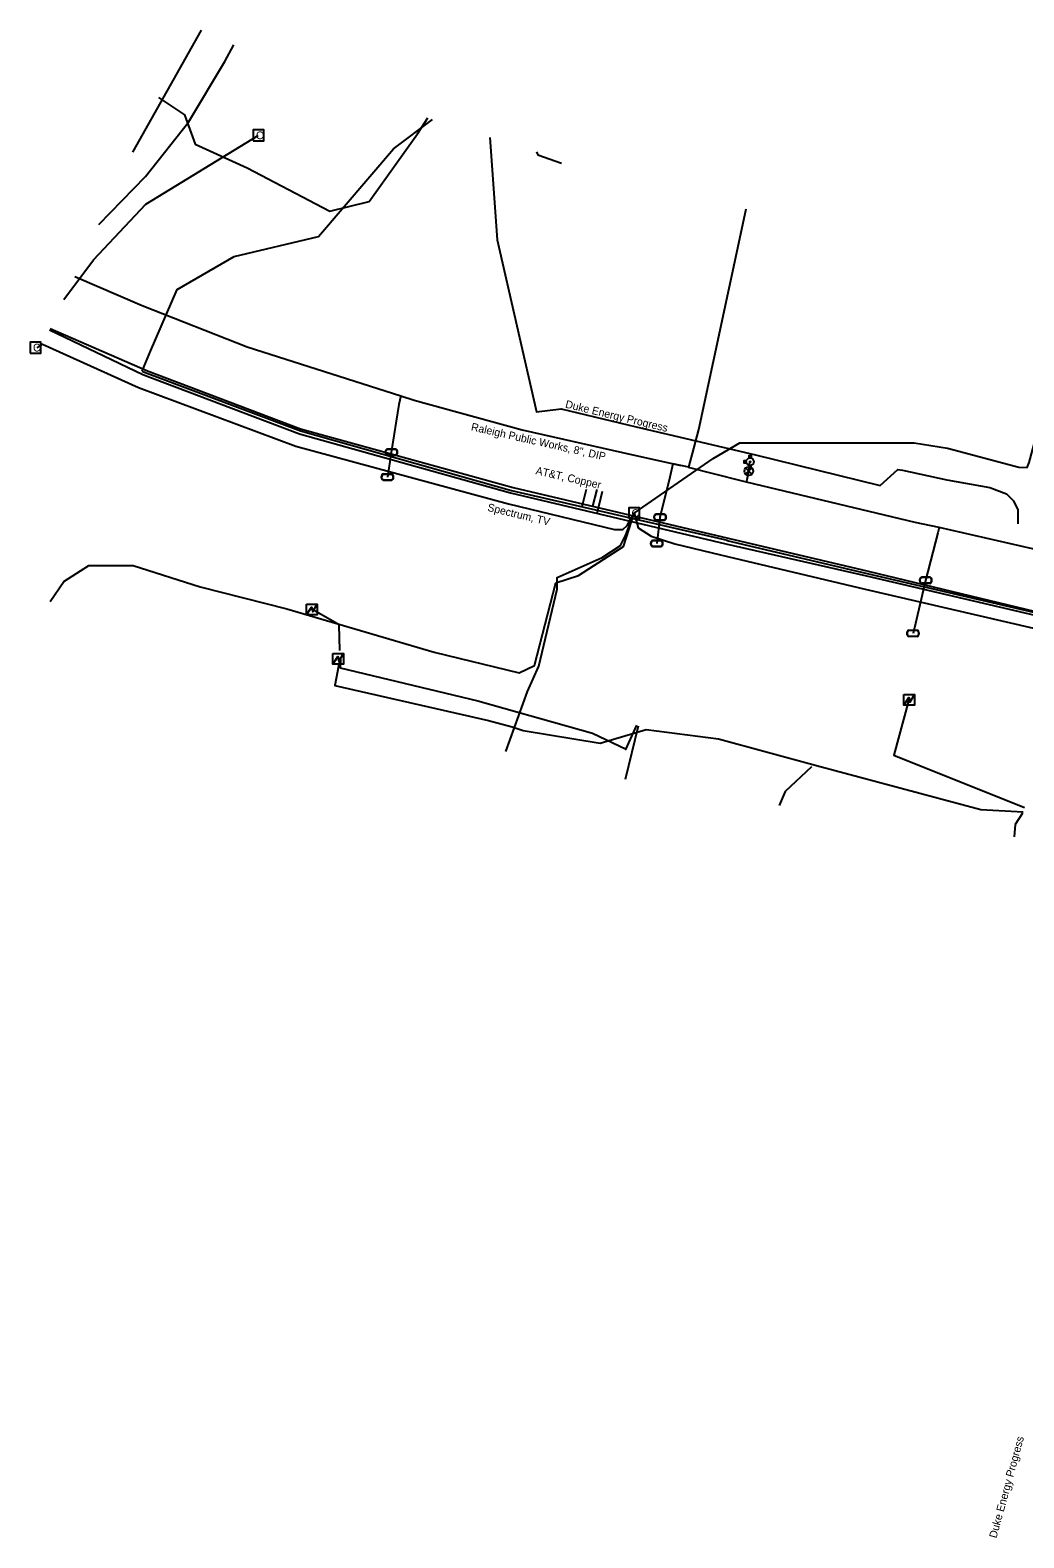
# Model space of a CAD drawing. Extents: x 2070721 to 2083039, y 729290 to 737883.
# Drawn here: x 2081558 to 2082068, y 735849 to 736623 of the extents above; entities that cross this region are included whole.
import ezdxf

# ---------------------------------------------------------------- set-up
doc = ezdxf.new("R2010")
doc.units = 0
for name, color, linetype in [('Cogo Default Point CELL', 7, 'Continuous'), ('COGO Default Point Elevation', 7, 'Continuous'), ('COGO Default Point Number', 7, 'Continuous'), ('Exist Utilities Gas UG Line SUE Cogo Point CELL', 7, 'Continuous'), ('Exist Utilities Gas Valve Cogo Elevation', 7, 'Continuous'), ('Exist Utilities Telephone Hand Hole Cogo Elevation', 7, 'Continuous'), ('Exist Utilities Telephone UG Cable SUE LOS C Cogo Number', 7, 'Continuous'), ('Exist Utilities Telephone UG FO Cogo Point CELL', 7, 'Continuous'), ('Exist Utilities TV Pedestal Cogo Elevation', 7, 'Continuous'), ('Exist Utilities TV UG Cable Cogo Point CELL', 7, 'Continuous'), ('Exist Utilities TV UG Cable SUE LOS C Cogo Comment', 7, 'Continuous'), ('Exist Utilities TV UG Cable SUE LOS C Cogo Elevation', 7, 'Continuous'), ('Exist Utilities Water Meter CELL', 7, 'Continuous'), ('Exist Utilities Water Meter Cogo Number', 7, 'Continuous')]:
    doc.layers.add(name, color=color, linetype=linetype)

msp = doc.modelspace()

# ---------------------------------------------------------------- linework, layer by layer
at = {"layer": 'Cogo Default Point CELL'}
for p, q in [((2081675.3, 736568.67), (2081675.3, 736568.67)), ((2081560.99, 736459.77), (2081560.99, 736459.77)), ((2081867.92, 736374.85), (2081867.92, 736374.85))]:
    msp.add_line(p, q, dxfattribs=at)
for points in [[(2081672.53, 736565.9), (2081678.07, 736565.9), (2081678.07, 736571.45), (2081672.53, 736571.45), (2081672.53, 736565.9)], [(2081558.22, 736456.99), (2081563.77, 736456.99), (2081563.77, 736462.55), (2081558.22, 736462.55), (2081558.22, 736456.99)], [(2081865.15, 736372.08), (2081870.7, 736372.08), (2081870.7, 736377.62), (2081865.15, 736377.62), (2081865.15, 736372.08)]]:
    msp.add_lwpolyline(points, dxfattribs=at)
at = {"layer": 'COGO Default Point Elevation'}
msp.add_lwpolyline([(2081928.26, 736398.02), (2081925.1, 736394.86), (2081926.68, 736396.44), (2081928.26, 736394.86), (2081925.1, 736398.02)], dxfattribs=at)
msp.add_circle((2081926.68, 736396.44), 2.23, dxfattribs=at)
at = {"layer": 'COGO Default Point Number'}
msp.add_line((2081927.4, 736401.2), (2081927.4, 736401.2), dxfattribs=at)
for points in [[(2081926.89, 736403.11), (2081926.89, 736404.4), (2081927.91, 736404.4), (2081927.91, 736403.09)], [(2081925.49, 736401.71), (2081924.2, 736401.71), (2081924.2, 736400.69), (2081925.49, 736400.69)], [(2081926.89, 736399.29), (2081926.89, 736398), (2081927.91, 736398), (2081927.91, 736399.31)]]:
    msp.add_lwpolyline(points, dxfattribs=at)
for radius in [1.98, 0.243]:
    msp.add_circle((2081927.4, 736401.2), radius, dxfattribs=at)
at = {"layer": 'Exist Utilities Gas Valve Cogo Elevation'}
for p, q in [((2081841.3, 736378.17), (2081843.56, 736387.2)), ((2081846.72, 736378.45), (2081848.94, 736386.91)), ((2081848.99, 736374.72), (2081851.73, 736386.2))]:
    msp.add_line(p, q, dxfattribs=at)
at = {"layer": 'Exist Utilities Telephone UG Cable SUE LOS C Cogo Number'}
for p, q in [((2081702.7, 736325.61), (2081702.7, 736325.61)), ((2081716.19, 736300.27), (2081716.19, 736300.27)), ((2082009, 736279.19), (2082009, 736279.19))]:
    msp.add_line(p, q, dxfattribs=at)
for points in [[(2081699.86, 736328.22), (2081705.41, 736328.22), (2081705.41, 736322.67), (2081699.86, 736322.67)], [(2081713.35, 736302.88), (2081718.9, 736302.88), (2081718.9, 736297.33), (2081713.35, 736297.33)], [(2082006.16, 736281.8), (2082011.71, 736281.8), (2082011.71, 736276.25), (2082006.16, 736276.25)]]:
    msp.add_lwpolyline(points, close=True, dxfattribs=at)
for points in [[(2081699.86, 736322.67), (2081702.5, 736326.61), (2081703.13, 736324.4), (2081705.41, 736328.22)], [(2081699.93, 736322.67), (2081702.5, 736326.4), (2081703.09, 736324.22), (2081705.41, 736328.07)], [(2081713.35, 736297.33), (2081715.99, 736301.27), (2081716.62, 736299.06), (2081718.9, 736302.88)], [(2081713.42, 736297.33), (2081715.99, 736301.06), (2081716.58, 736298.88), (2081718.9, 736302.73)], [(2082006.16, 736276.25), (2082008.8, 736280.19), (2082009.43, 736277.98), (2082011.71, 736281.8)], [(2082006.23, 736276.25), (2082008.8, 736279.98), (2082009.39, 736277.8), (2082011.71, 736281.65)]]:
    msp.add_lwpolyline(points, dxfattribs=at)
at = {"layer": 'Exist Utilities Telephone UG FO Cogo Point CELL'}
for p, q in [((2081743.45, 736406.13), (2081743.45, 736406.13)), ((2081741.43, 736393.35), (2081741.43, 736393.35)), ((2081881.24, 736372.78), (2081881.24, 736372.78)), ((2081879.54, 736359.27), (2081879.54, 736359.27)), ((2082017.46, 736340.42), (2082017.46, 736340.42)), ((2082010.93, 736313.18), (2082010.93, 736313.18))]:
    msp.add_line(p, q, dxfattribs=at)
for points in [[(2081745.49, 736404.57), (2081741.39, 736404.57)], [(2081745.49, 736404.43), (2081741.39, 736404.43)], [(2081741.41, 736407.83), (2081745.49, 736407.83)], [(2081741.41, 736407.69), (2081745.49, 736407.69)], [(2081743.47, 736391.79), (2081739.37, 736391.79)], [(2081743.47, 736391.65), (2081739.37, 736391.65)], [(2081739.39, 736395.05), (2081743.47, 736395.05)], [(2081739.39, 736394.91), (2081743.47, 736394.91)], [(2081879.2, 736374.48), (2081883.28, 736374.48)], [(2081879.2, 736374.34), (2081883.28, 736374.34)], [(2081883.28, 736371.22), (2081879.18, 736371.22)], [(2081883.28, 736371.08), (2081879.18, 736371.08)], [(2081881.58, 736357.71), (2081877.48, 736357.71)], [(2081881.58, 736357.57), (2081877.48, 736357.57)], [(2081877.5, 736360.97), (2081881.58, 736360.97)], [(2081877.5, 736360.83), (2081881.58, 736360.83)], [(2082015.42, 736342.12), (2082019.5, 736342.12)], [(2082015.42, 736341.98), (2082019.5, 736341.98)], [(2082019.5, 736338.86), (2082015.4, 736338.86)], [(2082019.5, 736338.72), (2082015.4, 736338.72)], [(2082012.97, 736311.62), (2082008.87, 736311.62)], [(2082012.97, 736311.48), (2082008.87, 736311.48)], [(2082008.89, 736314.88), (2082012.97, 736314.88)], [(2082008.89, 736314.74), (2082012.97, 736314.74)]]:
    msp.add_lwpolyline(points, dxfattribs=at)
for centre, radius, start, end in [((2081742.14, 736406.12), 1.86, 113.17804, 245.97939), ((2081742.15, 736406.12), 1.73, 115.30093, 243.78236), ((2081744.74, 736406.13), 1.86, 293.64832, 66.30838), ((2081744.75, 736406.13), 1.73, 295.12717, 64.87283), ((2081740.12, 736393.34), 1.86, 113.17804, 245.97939), ((2081740.13, 736393.34), 1.73, 115.30093, 243.78236), ((2081742.72, 736393.35), 1.86, 293.64832, 66.30838), ((2081742.73, 736393.35), 1.73, 295.12717, 64.87283), ((2081879.93, 736372.77), 1.86, 113.17804, 245.97939), ((2081879.94, 736372.77), 1.73, 115.30093, 243.78236), ((2081882.53, 736372.78), 1.86, 293.64832, 66.30838), ((2081882.54, 736372.78), 1.73, 295.12717, 64.87283), ((2081878.23, 736359.26), 1.86, 113.17804, 245.97939), ((2081878.24, 736359.26), 1.73, 115.30093, 243.78236), ((2081880.83, 736359.27), 1.86, 293.64832, 66.30838), ((2081880.84, 736359.27), 1.73, 295.12717, 64.87283), ((2082016.15, 736340.41), 1.86, 113.17804, 245.97939), ((2082016.16, 736340.41), 1.73, 115.30093, 243.78236), ((2082018.75, 736340.42), 1.86, 293.64832, 66.30838), ((2082018.76, 736340.42), 1.73, 295.12717, 64.87283), ((2082009.62, 736313.17), 1.86, 113.17804, 245.97939), ((2082009.63, 736313.17), 1.73, 115.30093, 243.78236), ((2082012.22, 736313.18), 1.86, 293.64832, 66.30838), ((2082012.23, 736313.18), 1.73, 295.12717, 64.87283)]:
    msp.add_arc(centre, radius, start, end, dxfattribs=at)
at = {"layer": 'Exist Utilities TV Pedestal Cogo Elevation'}
for points in [[(2081610.89, 736559.97), (2081646, 736622.62)], [(2081895.92, 736398.39), (2081898.48, 736408.05), (2081901.09, 736417.77), (2081924.13, 736525.36), (2081925.42, 736531.03)], [(2081581.04, 736496.29), (2081615.73, 736481.45), (2081669.42, 736460.1), (2081748.23, 736434.96)], [(2081748.23, 736434.96), (2081747.28, 736430.58), (2081743.34, 736405.99), (2081741.41, 736393.34)], [(2081748.23, 736434.96), (2081755.16, 736432.79), (2081810.5, 736417.55), (2081861.99, 736405.96), (2081891.89, 736399.27)], [(2081887.85, 736400.15), (2081886.16, 736393.27), (2081881.11, 736372.66), (2081879.62, 736359.28)], [(2081895.92, 736398.39), (2081887.85, 736400.15)], [(2081925.63, 736390.78), (2081922.81, 736391.44), (2081895.86, 736398.32)], [(2081925.63, 736390.78), (2081925.87, 736392.04), (2081926.72, 736396.45), (2081927.31, 736401.22)], [(2082024.3, 736367.53), (2082012.08, 736370.04), (2081925.63, 736390.78)], [(2082024.3, 736367.53), (2082023.59, 736364.74), (2082017.34, 736340.25), (2082011.01, 736313.15)], [(2082096.13, 736351.01), (2082024.3, 736367.53)]]:
    msp.add_lwpolyline(points, dxfattribs=at)
at = {"layer": 'Exist Utilities TV UG Cable Cogo Point CELL'}
for points in [[(2081615.72, 736447.72), (2081619.87, 736457.87), (2081633.54, 736489.64), (2081662.78, 736506.59), (2081706.01, 736516.81), (2081744.57, 736561.71), (2081764.57, 736576.83)], [(2081568.17, 736468.83), (2081615.92, 736445.96), (2081696.31, 736415.49), (2081804.57, 736385.24), (2081915.03, 736359.08), (2081987.17, 736342.62), (2082073.48, 736322.55), (2082138.89, 736307.01), (2082220.41, 736288.62), (2082293.92, 736270.7)], [(2081568.48, 736469.51), (2081618.39, 736447.85), (2081696.88, 736418.07), (2081805.87, 736388.07), (2081916.17, 736362.01), (2081987.94, 736345.05), (2082073.78, 736324.33), (2082139.32, 736308.59), (2082221.63, 736291.02), (2082296.5, 736270.5)], [(2081615.72, 736447.72), (2081617.75, 736446.75), (2081696.77, 736417.12), (2081805.08, 736386.54), (2081915.58, 736360.92), (2081915.48, 736360.89), (2081987.51, 736343.92), (2082073.49, 736323.81), (2082139.92, 736308.03), (2082220.81, 736289.54), (2082294.45, 736271.08)]]:
    msp.add_lwpolyline(points, dxfattribs=at)
at = {"layer": 'Exist Utilities TV UG Cable SUE LOS C Cogo Comment'}
msp.add_line((2081869.95, 736265.5), (2081863.38, 736238.25), dxfattribs=at)
for points in [[(2081593.51, 736522.9), (2081617.43, 736547.49), (2081639.43, 736575.38), (2081658.05, 736606.46), (2081662.69, 736615.09)], [(2081624.06, 736588.07), (2081637.35, 736579.12), (2081642.78, 736564.1), (2081669.56, 736552.07), (2081711.84, 736529.72), (2081732.02, 736534.7), (2081756.88, 736569.41), (2081762.09, 736577.62)], [(2081793.97, 736567.61), (2081797.64, 736515.06), (2081817.81, 736426.78), (2081830.54, 736428.4), (2081868.97, 736419.19), (2081930.14, 736404.7), (2081994.03, 736388.95), (2082003.1, 736397.16), (2082005.52, 736396.93)], [(2081817.86, 736560.12), (2081818.61, 736558.64), (2081830.67, 736554.47)], [(2082005.52, 736396.93), (2082028.31, 736391.85), (2082050.28, 736387.92)], [(2082050.28, 736387.92), (2082058.9, 736384.67), (2082062.45, 736381.12), (2082064.71, 736376.6), (2082064.71, 736369.34)], [(2081716.95, 736304.41), (2081716.62, 736317.49), (2081702.59, 736325.64)], [(2081716.93, 736299.92), (2081714.46, 736286.45), (2081793.21, 736268.43), (2081805.43, 736265.26), (2081810.95, 736263.37)], [(2081717.34, 736300.03), (2081717.21, 736295.55), (2081787.8, 736278.61), (2081846.5, 736261.98), (2081863.85, 736253.78), (2081863.67, 736253.65), (2081869.34, 736266.08)], [(2082008.8, 736279.06), (2082001.18, 736250.65), (2082068.04, 736223.8)], [(2081810.95, 736263.37), (2081850.56, 736256.87), (2081874.02, 736263.85), (2081911.12, 736259.04), (2081961.37, 736245.31), (2082045.75, 736222.88), (2082067.35, 736221.62)], [(2081958.92, 736244.7), (2081945.38, 736232.03), (2081942.33, 736224.89)], [(2082067.1, 736220.9), (2082063.38, 736215.05), (2082062.82, 736208.84)]]:
    msp.add_lwpolyline(points, dxfattribs=at)
at = {"layer": 'Exist Utilities TV UG Cable SUE LOS C Cogo Elevation'}
for points in [[(2081575.5, 736484.47), (2081590.65, 736504.86), (2081617.46, 736533.4), (2081675.12, 736568.6)], [(2081561.77, 736459.66), (2081564.51, 736461.5), (2081613.71, 736439.34), (2081694.53, 736409.12), (2081803.54, 736379.56), (2081857.88, 736366.5), (2081862.11, 736366.5), (2081864.43, 736368.45), (2081867.92, 736374.85)], [(2081867.92, 736374.85), (2081908.54, 736402.92), (2081922.2, 736410.85), (2081955.72, 736410.85), (2081976.56, 736410.85), (2082011.49, 736410.85), (2082028.68, 736408.17), (2082065.29, 736398.47), (2082069.56, 736398.28), (2082070.52, 736400.88), (2082075.6, 736419.83), (2082081.77, 736427.24), (2082099.8, 736423.88), (2082126.06, 736418.32), (2082170.39, 736408.66), (2082225.96, 736394.95), (2082242.36, 736398.41), (2082249.96, 736397.77)], [(2081568.39, 736329.45), (2081575.55, 736339.8), (2081588.34, 736348.06), (2081611.08, 736348.06), (2081645.32, 736337.04), (2081689.76, 736325.78), (2081765.44, 736303.46), (2081808.94, 736292.9), (2081816.89, 736296.62), (2081827.8, 736339.07), (2081839.46, 736342.78), (2081862.53, 736357.65), (2081867.92, 736374.85)], [(2081802.09, 736252.59), (2081813.22, 736283.38), (2081819.12, 736296.34), (2081828.46, 736335.85), (2081828.46, 736341.85), (2081851.47, 736352.07), (2081860.9, 736358.31), (2081863.63, 736363.74), (2081867.92, 736374.85)], [(2081867.92, 736374.85), (2081869.92, 736367.25), (2081876.67, 736362.95), (2081888.78, 736359.07), (2081912.22, 736353.44), (2081986.37, 736335.81), (2082072.78, 736315.77), (2082135.75, 736299.21), (2082217.86, 736275.92), (2082262.9, 736250.17), (2082262.99, 736250.08), (2082292.59, 736221.95), (2082307.6, 736199.94)]]:
    msp.add_lwpolyline(points, dxfattribs=at)

# ---------------------------------------------------------------- texts
at = {"layer": 'Cogo Default Point CELL'}
for p in [(2081673.99, 736566.67), (2081559.68, 736457.77), (2081866.61, 736372.85)]:
    msp.add_text('C', height=4, dxfattribs=at).set_placement(p)
at = {"layer": 'Exist Utilities Gas UG Line SUE Cogo Point CELL'}
msp.add_text('Raleigh Public Works, 8", DIP ', height=4, rotation=347.31166, dxfattribs=at).set_placement((2081784.04, 736417.36))
at = {"layer": 'Exist Utilities Telephone Hand Hole Cogo Elevation'}
msp.add_text('Spectrum, TV', height=4, rotation=346.48592, dxfattribs=at).set_placement((2081792.45, 736376.06))
at = {"layer": 'Exist Utilities Water Meter CELL'}
for rotation, p in [(346.52288, (2081832.36, 736429.01)), (74.74215, (2082053.73, 735848.73))]:
    msp.add_text('Duke Energy Progress', height=4, rotation=rotation, dxfattribs=at).set_placement(p)
at = {"layer": 'Exist Utilities Water Meter Cogo Number'}
msp.add_text('AT&T, Copper', height=4, rotation=347.1366, dxfattribs=at).set_placement((2081817.17, 736394.89))

doc.saveas('drawing.dxf')
